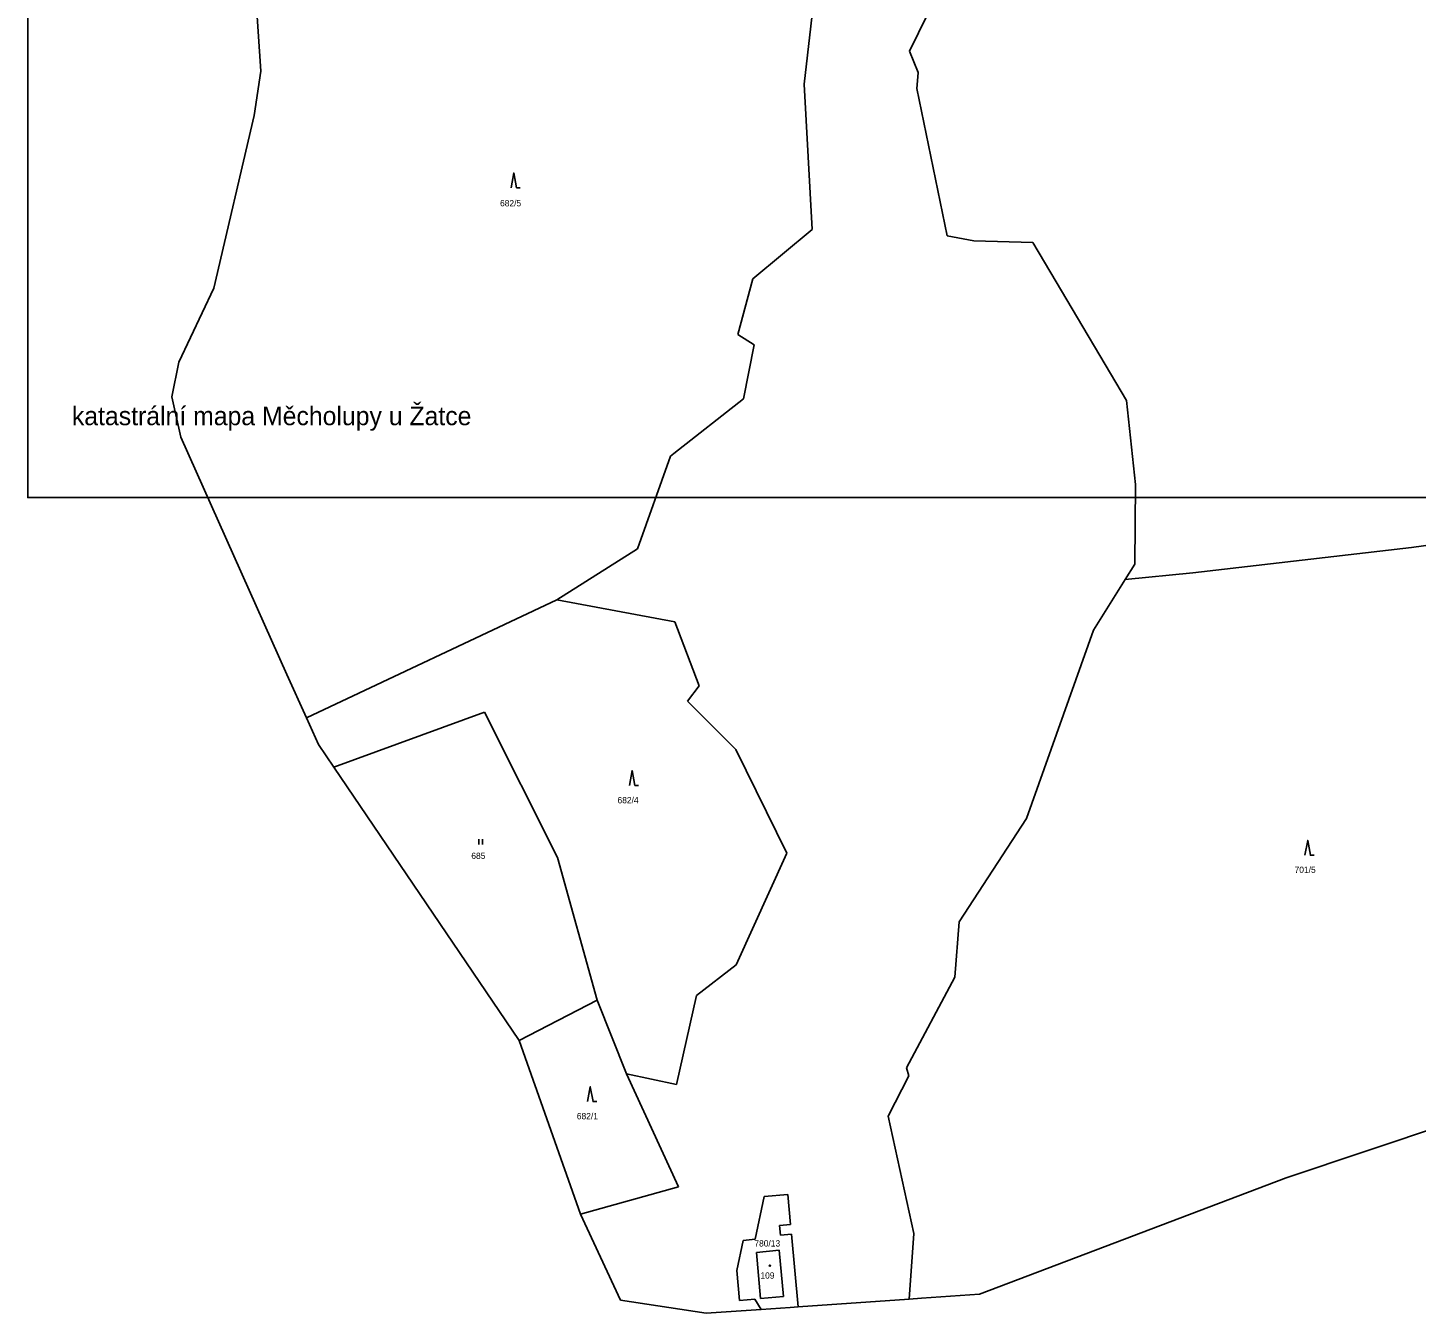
# Model space of a CAD drawing. Extents: x -801907 to -800293, y -1016964 to -1015684.
# Drawn here: x -801306.1 to -800931.6, y -1016963.5 to -1016616.9 of the extents above; entities that cross this region are included whole.
import ezdxf

# ---------------------------------------------------------------- set-up
doc = ezdxf.new("R2010")
doc.units = 0
for name, color, linetype in [('Default', 7, 'Continuous'), ('KLADY_ZMVM', 7, 'Continuous'), ('KN_HRANICE', 7, 'Continuous'), ('KN_KULTURY', 7, 'Continuous'), ('KN_PARCELY', 7, 'Continuous'), ('LEGENDA', 7, 'Continuous')]:
    doc.layers.add(name, color=color, linetype=linetype)

# ---------------------------------------------------------------- blocks, each defined once
blk = doc.blocks.new('306')
at = {"layer": 'Default'}
for p, q in [((-0.5, 1.5), (-0.5, 0)), ((0.5, 0), (0.5, 1.5))]:
    blk.add_line(p, q, dxfattribs=at)
blk = doc.blocks.new('308')
at = {"layer": 'Default'}
blk.add_lwpolyline([(-0.75, 0), (0, 4), (0.75, 0), (1.75, 0)], dxfattribs=at)
blk = doc.blocks.new('402')
at = {"layer": 'Default'}
blk.add_lwpolyline([(0.09, 0.15), (0.18, 0), (0.09, -0.15), (-0.09, -0.15), (-0.18, 0), (-0.09, 0.15), (0.09, 0.15)], dxfattribs=at)

msp = doc.modelspace()

# ---------------------------------------------------------------- linework, layer by layer
at = {"layer": 'KN_HRANICE'}
for p, q in [((-801048.49, -1016582.57), (-801068.25, -1016623.2)), ((-801245.16, -1016599.53), (-801243.27, -1016628.57)), ((-801096.7, -1016632.06), (-801092.82, -1016598.49)), ((-801068.25, -1016623.2), (-801065.96, -1016628.91)), ((-801243.27, -1016628.57), (-801245.06, -1016640.51)), ((-801066.14, -1016631.19), (-801066.3, -1016633.24)), ((-801065.96, -1016628.91), (-801066.14, -1016631.19)), ((-801094.54, -1016671.27), (-801096.7, -1016632.06)), ((-801066.3, -1016633.24), (-801058.15, -1016672.95)), ((-801255.91, -1016687.07), (-801245.06, -1016640.51)), ((-801110.5, -1016684.56), (-801094.54, -1016671.27)), ((-801058.15, -1016672.95), (-801050.94, -1016674.31)), ((-801050.94, -1016674.31), (-801034.98, -1016674.73)), ((-801034.98, -1016674.73), (-801028.66, -1016685.38)), ((-801255.91, -1016687.07), (-801265.38, -1016707.01)), ((-801114.53, -1016699.61), (-801110.5, -1016684.56)), ((-801028.66, -1016685.38), (-801009.71, -1016717.33)), ((-801110.14, -1016702.4), (-801114.53, -1016699.61)), ((-801113.09, -1016716.95), (-801110.14, -1016702.4)), ((-801265.38, -1016707.01), (-801267.26, -1016716.41)), ((-801267.26, -1016716.41), (-801264.86, -1016727.26)), ((-801131.83, -1016731.7), (-801113.09, -1016716.95)), ((-801009.71, -1016717.33), (-801007.26, -1016739.98)), ((-801264.86, -1016727.26), (-801236.19, -1016791.22)), ((-801141.65, -1016757.37), (-801132.73, -1016732.41)), ((-801132.73, -1016732.41), (-801131.83, -1016731.7)), ((-801007.26, -1016739.98), (-801007.51, -1016761.47)), ((-800932.89, -1016756.98), (-800846.15, -1016745.38)), ((-801163.4, -1016771.13), (-801141.65, -1016757.37)), ((-800932.89, -1016756.98), (-800991.82, -1016763.86)), ((-801007.51, -1016761.47), (-801010.08, -1016765.6)), ((-801010.08, -1016765.6), (-801018.62, -1016779.34)), ((-800991.82, -1016763.86), (-801010.08, -1016765.6)), ((-801163.4, -1016771.13), (-801230.93, -1016802.94)), ((-801131.53, -1016777.03), (-801163.4, -1016771.13)), ((-801124.98, -1016794.3), (-801131.53, -1016777.03)), ((-801018.62, -1016779.34), (-801036.69, -1016830.07)), ((-801236.19, -1016791.22), (-801230.93, -1016802.94)), ((-801128.15, -1016798.48), (-801124.98, -1016794.3)), ((-801115.13, -1016811.47), (-801128.15, -1016798.48)), ((-801230.93, -1016802.94), (-801227.69, -1016810.17)), ((-801182.9, -1016801.41), (-801223.54, -1016816.29)), ((-801182.9, -1016801.41), (-801163.18, -1016840.62)), ((-801227.69, -1016810.17), (-801223.54, -1016816.29)), ((-801101.38, -1016839.47), (-801115.13, -1016811.47)), ((-801223.54, -1016816.29), (-801173.56, -1016890)), ((-801036.69, -1016830.07), (-801054.84, -1016857.97)), ((-801163.18, -1016840.62), (-801152.53, -1016879.07)), ((-801114.98, -1016869.57), (-801101.38, -1016839.47)), ((-801054.84, -1016857.97), (-801056.01, -1016872.88)), ((-801125.7, -1016877.8), (-801114.98, -1016869.57)), ((-801056.01, -1016872.88), (-801069.07, -1016897.37)), ((-801152.53, -1016879.07), (-801173.56, -1016890)), ((-801144.58, -1016898.92), (-801152.53, -1016879.07)), ((-801131.1, -1016901.79), (-801125.7, -1016877.8)), ((-801173.56, -1016890), (-801157.02, -1016936.79)), ((-801069.07, -1016897.37), (-801068.48, -1016899.49)), ((-801130.62, -1016929.41), (-801144.58, -1016898.92)), ((-801144.58, -1016898.92), (-801131.1, -1016901.79)), ((-801068.48, -1016899.49), (-801073.99, -1016910.36)), ((-801073.99, -1016910.36), (-801067.12, -1016942.01)), ((-800966.67, -1016927.02), (-800919.72, -1016911.28)), ((-801049.4, -1016958.4), (-800966.67, -1016927.02)), ((-801157.02, -1016936.79), (-801130.62, -1016929.41)), ((-801107.46, -1016932.05), (-801101.09, -1016931.47)), ((-801101.09, -1016931.47), (-801100.35, -1016939.54)), ((-801107.46, -1016932.05), (-801109.88, -1016943.55)), ((-801157.02, -1016936.79), (-801146.24, -1016959.95)), ((-801100.35, -1016939.54), (-801103.29, -1016939.8)), ((-801103.29, -1016939.8), (-801103.05, -1016942.44)), ((-801103.05, -1016942.44), (-801100.11, -1016942.18)), ((-801100.11, -1016942.18), (-801098.33, -1016961.78)), ((-801067.12, -1016942.01), (-801068.35, -1016959.71)), ((-801113.17, -1016943.85), (-801114.84, -1016951.99)), ((-801109.88, -1016943.55), (-801113.17, -1016943.85)), ((-801103.39, -1016946.53), (-801109.56, -1016947.09)), ((-801108.43, -1016959.54), (-801109.56, -1016947.09)), ((-801102.26, -1016958.98), (-801103.39, -1016946.53)), ((-801114.11, -1016960.06), (-801114.84, -1016951.99)), ((-801146.24, -1016959.95), (-801123.1, -1016963.5)), ((-801110.03, -1016959.68), (-801114.11, -1016960.06)), ((-801110.03, -1016959.68), (-801108.28, -1016962.47)), ((-801102.26, -1016958.98), (-801108.43, -1016959.54)), ((-801098.33, -1016961.78), (-801068.35, -1016959.71)), ((-801068.35, -1016959.71), (-801065.05, -1016959.48)), ((-801065.05, -1016959.48), (-801049.4, -1016958.4)), ((-801123.1, -1016963.5), (-801108.28, -1016962.47)), ((-801108.28, -1016962.47), (-801100.45, -1016961.93)), ((-801100.45, -1016961.93), (-801098.33, -1016961.78))]:
    msp.add_line(p, q, dxfattribs=at)
at = {"layer": 'LEGENDA'}
msp.add_lwpolyline([(-801306.12, -1016323.56), (-800712.12, -1016323.56), (-800712.12, -1016743.56), (-801306.12, -1016743.56)], close=True, dxfattribs=at)

# ---------------------------------------------------------------- block references
at = {"layer": 'KN_KULTURY'}
for name, p in [('308', (-801175, -1016660)), ('308', (-801143.08, -1016821.17)), ('306', (-801183.93, -1016837.13)), ('308', (-800960.85, -1016840.02)), ('308', (-801154.39, -1016906.41)), ('402', (-801105.93, -1016950.65))]:
    msp.add_blockref(name, p, dxfattribs=at)

# ---------------------------------------------------------------- texts
at = {"layer": 'KLADY_ZMVM'}
msp.add_text('katastrální mapa Měcholupy u Žatce', height=5, dxfattribs=at).set_placement((-801294.21, -1016724.03))
at = {"layer": 'KN_PARCELY'}
for s, p in [('682/5', (-801178.72, -1016665.02)), ('682/4', (-801147.03, -1016825.99)), ('685', (-801186.47, -1016841)), ('701/5', (-800964.39, -1016844.76)), ('682/1', (-801158, -1016911.2)), ('780/13', (-801110.11, -1016945.51)), ('109', (-801108.48, -1016954.18))]:
    msp.add_text(s, height=1.7, dxfattribs=at).set_placement(p)

doc.saveas('drawing.dxf')
